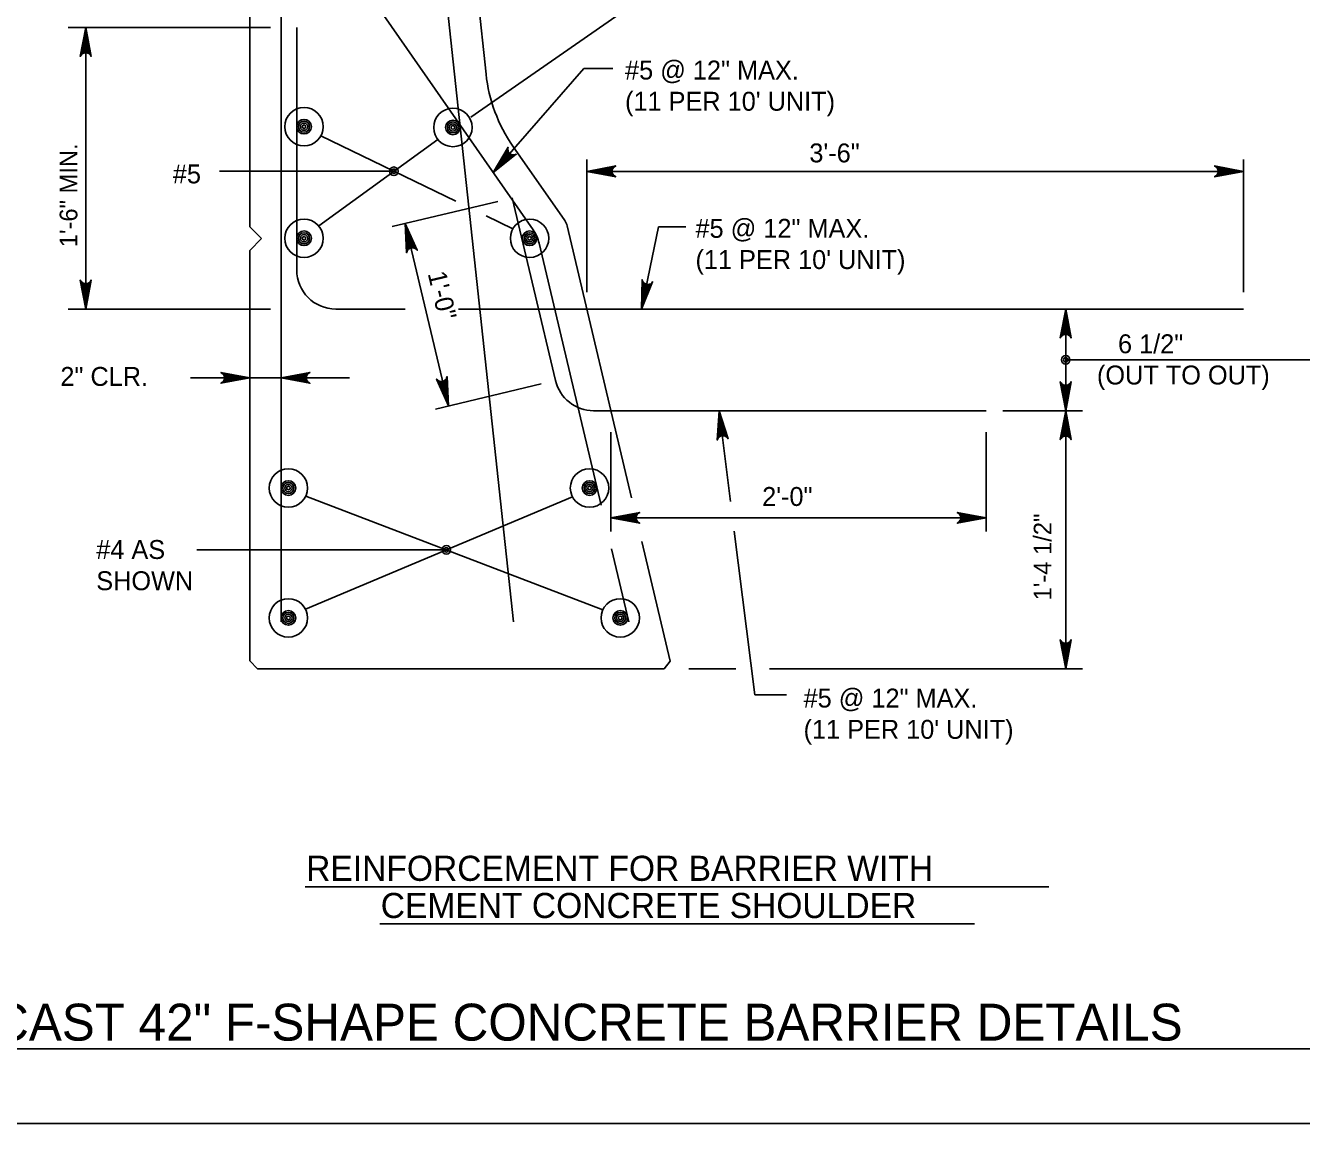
# Model space of a CAD drawing. Extents: x 638167 to 640248, y 296544 to 298920.
# Drawn here: x 638355.5 to 638562.8, y 297153.5 to 297331.8 of the extents above; entities that cross this region are included whole.
import ezdxf

# ---------------------------------------------------------------- set-up
doc = ezdxf.new("R2010")
doc.units = 0
for name, color, linetype in [('1', 7, 'Continuous'), ('50', 7, 'Continuous'), ('57', 7, 'Continuous')]:
    doc.layers.add(name, color=color, linetype=linetype)

# ---------------------------------------------------------------- blocks, each defined once
blk = doc.blocks.new('DIMDOT')
at = {"layer": '57'}
for radius in [2, 1]:
    blk.add_circle((0, 0), radius, dxfattribs=at)
blk = doc.blocks.new('BAR')
at = {"layer": '50'}
for radius in [2, 1.5, 1, 0.5]:
    blk.add_circle((0, 0), radius, dxfattribs=at)

msp = doc.modelspace()

# ---------------------------------------------------------------- linework, layer by layer
at = {"layer": '1'}
for p, q in [((638391.93, 297396.88), (638391.93, 297299.09)), ((638422.65, 297396.51), (638430.31, 297323.92)), ((638397.01, 297234.95), (638397.01, 297389.89)), ((638418.01, 297390.3), (638434.79, 297234.95)), ((638408.65, 297340.68), (638437.96, 297298.6)), ((638427.85, 297316.9), (638456.9, 297337.13)), ((638395.32, 297331.47), (638362.42, 297331.47)), ((638365.28, 297331.47), (638365.28, 297285.75)), ((638399.55, 297292.1), (638399.55, 297331.47)), ((638446.22, 297324.82), (638431.47, 297307.92)), ((638446.22, 297324.82), (638450.88, 297324.82)), ((638403.12, 297299.26), (638422.47, 297313.31)), ((638403.47, 297313.86), (638425.4, 297303.25)), ((638434.67, 297312.21), (638443.09, 297300.12)), ((638446.67, 297288.51), (638446.67, 297310.06)), ((638553.35, 297288.51), (638553.35, 297310.06)), ((638386.99, 297308.12), (638415.33, 297308.12)), ((638446.67, 297308.11), (638553.35, 297308.11)), ((638432.25, 297303.24), (638415.08, 297299.17)), ((638434.57, 297303.79), (638441.6, 297274.13)), ((638430.31, 297300.87), (638434.66, 297298.77)), ((638391.93, 297299.09), (638393.84, 297297.18)), ((638417.18, 297299.67), (638424.21, 297270.01)), ((638443.48, 297299.25), (638453.94, 297255.08)), ((638458.33, 297299.12), (638455.56, 297285.75)), ((638462.76, 297299.12), (638458.33, 297299.12)), ((638391.93, 297295.28), (638393.84, 297297.18)), ((638438.92, 297296.44), (638449, 297253.91)), ((638391.93, 297295.28), (638391.93, 297228.6)), ((638395.32, 297285.75), (638362.42, 297285.75)), ((638405.9, 297285.75), (638417.17, 297285.75)), ((638425.86, 297285.75), (638553.35, 297285.75)), ((638524.47, 297285.75), (638524.47, 297227.33)), ((638524.47, 297277.5), (638564.39, 297277.5)), ((638382.31, 297274.57), (638408.14, 297274.57)), ((638439.28, 297273.58), (638422.1, 297269.51)), ((638447.78, 297269.24), (638511.55, 297269.24)), ((638470.02, 297254.5), (638468.16, 297269.24)), ((638514.24, 297269.24), (638527.2, 297269.24)), ((638450.59, 297265.76), (638450.59, 297249.64)), ((638511.55, 297265.76), (638511.55, 297249.64)), ((638444.34, 297255.27), (638400.99, 297237)), ((638401.04, 297255.38), (638449.28, 297236.9)), ((638450.59, 297251.85), (638511.55, 297251.85)), ((638473.98, 297223.07), (638470.63, 297249.69)), ((638383.34, 297246.64), (638423.86, 297246.64)), ((638450.68, 297246.8), (638453.49, 297234.95)), ((638455.62, 297247.97), (638460.22, 297228.57)), ((638391.93, 297228.6), (638393.2, 297227.33)), ((638460.22, 297228.57), (638459.24, 297227.33)), ((638393.2, 297227.33), (638459.24, 297227.33)), ((638463.26, 297227.33), (638470.91, 297227.33)), ((638476.37, 297227.33), (638527.2, 297227.33)), ((638479.1, 297223.07), (638473.98, 297223.07)), ((638400.95, 297191.93), (638521.73, 297191.93)), ((638413.06, 297185.89), (638509.68, 297185.89)), ((638332.86, 297165.59), (638596.87, 297165.59)), ((638205.78, 297153.48), (638991.78, 297153.48))]:
    msp.add_line(p, q, dxfattribs=at)
for points in [[(638365.28, 297331.47), (638366.16, 297326.78), (638366.04, 297326.96), (638365.91, 297327.14), (638365.76, 297327.23), (638365.6, 297327.33), (638365.44, 297327.35), (638365.28, 297327.38), (638365.13, 297327.35), (638364.97, 297327.33), (638364.81, 297327.23), (638364.65, 297327.14), (638364.53, 297326.96), (638364.4, 297326.78), (638365.28, 297331.47), (638364.53, 297326.96), (638364.65, 297327.14), (638365.28, 297331.47), (638364.81, 297327.23), (638364.97, 297327.33), (638365.28, 297331.47), (638365.13, 297327.35), (638365.28, 297327.38), (638365.28, 297331.47), (638365.44, 297327.35), (638365.6, 297327.33), (638365.28, 297331.47), (638365.76, 297327.23), (638365.91, 297327.14), (638365.28, 297331.47), (638366.04, 297326.96)], [(638431.47, 297307.92), (638433.9, 297312.04), (638433.87, 297311.82), (638433.85, 297311.6), (638433.9, 297311.43), (638433.96, 297311.25), (638434.06, 297311.13), (638434.16, 297311), (638434.3, 297310.92), (638434.44, 297310.84), (638434.62, 297310.8), (638434.8, 297310.77), (638435.01, 297310.82), (638435.22, 297310.88), (638431.47, 297307.92), (638435.01, 297310.82), (638434.8, 297310.77), (638431.47, 297307.92), (638434.62, 297310.8), (638434.44, 297310.84), (638431.47, 297307.92), (638434.3, 297310.92), (638434.16, 297311), (638431.47, 297307.92), (638434.06, 297311.13), (638433.96, 297311.25), (638431.47, 297307.92), (638433.9, 297311.43), (638433.85, 297311.6), (638431.47, 297307.92), (638433.87, 297311.82)], [(638446.67, 297308.11), (638451.37, 297308.99), (638451.19, 297308.87), (638451.01, 297308.74), (638450.92, 297308.58), (638450.82, 297308.43), (638450.8, 297308.27), (638450.77, 297308.11), (638450.8, 297307.95), (638450.82, 297307.8), (638450.92, 297307.64), (638451.01, 297307.48), (638451.19, 297307.36), (638451.37, 297307.23), (638446.67, 297308.11), (638451.19, 297307.36), (638451.01, 297307.48), (638446.67, 297308.11), (638450.92, 297307.64), (638450.82, 297307.8), (638446.67, 297308.11), (638450.8, 297307.95), (638450.77, 297308.11), (638446.67, 297308.11), (638450.8, 297308.27), (638450.82, 297308.43), (638446.67, 297308.11), (638450.92, 297308.58), (638451.01, 297308.74), (638446.67, 297308.11), (638451.19, 297308.87)], [(638553.35, 297308.11), (638548.66, 297307.23), (638548.84, 297307.36), (638549.02, 297307.48), (638549.11, 297307.64), (638549.21, 297307.8), (638549.23, 297307.95), (638549.26, 297308.11), (638549.23, 297308.27), (638549.21, 297308.43), (638549.11, 297308.58), (638549.02, 297308.74), (638548.84, 297308.87), (638548.66, 297308.99), (638553.35, 297308.11), (638548.84, 297308.87), (638549.02, 297308.74), (638553.35, 297308.11), (638549.11, 297308.58), (638549.21, 297308.43), (638553.35, 297308.11), (638549.23, 297308.27), (638549.26, 297308.11), (638553.35, 297308.11), (638549.23, 297307.95), (638549.21, 297307.8), (638553.35, 297308.11), (638549.11, 297307.64), (638549.02, 297307.48), (638553.35, 297308.11), (638548.84, 297307.36)], [(638417.18, 297299.67), (638419.12, 297295.3), (638418.96, 297295.45), (638418.79, 297295.6), (638418.62, 297295.65), (638418.44, 297295.71), (638418.28, 297295.7), (638418.12, 297295.69), (638417.98, 297295.62), (638417.83, 297295.56), (638417.7, 297295.43), (638417.57, 297295.31), (638417.49, 297295.1), (638417.41, 297294.9), (638417.18, 297299.67), (638417.49, 297295.1), (638417.57, 297295.31), (638417.18, 297299.67), (638417.7, 297295.43), (638417.83, 297295.56), (638417.18, 297299.67), (638417.98, 297295.62), (638418.12, 297295.69), (638417.18, 297299.67), (638418.28, 297295.7), (638418.44, 297295.71), (638417.18, 297299.67), (638418.62, 297295.65), (638418.79, 297295.6), (638417.18, 297299.67), (638418.96, 297295.45)], [(638365.28, 297285.75), (638364.4, 297290.45), (638364.53, 297290.27), (638364.65, 297290.09), (638364.81, 297290), (638364.97, 297289.9), (638365.13, 297289.88), (638365.28, 297289.85), (638365.44, 297289.88), (638365.6, 297289.9), (638365.76, 297290), (638365.91, 297290.09), (638366.04, 297290.27), (638366.16, 297290.45), (638365.28, 297285.75), (638366.04, 297290.27), (638365.91, 297290.09), (638365.28, 297285.75), (638365.76, 297290), (638365.6, 297289.9), (638365.28, 297285.75), (638365.44, 297289.88), (638365.28, 297289.85), (638365.28, 297285.75), (638365.13, 297289.88), (638364.97, 297289.9), (638365.28, 297285.75), (638364.81, 297290), (638364.65, 297290.09), (638365.28, 297285.75), (638364.53, 297290.27)], [(638455.56, 297285.75), (638455.65, 297290.53), (638455.74, 297290.33), (638455.82, 297290.13), (638455.96, 297290), (638456.09, 297289.88), (638456.24, 297289.82), (638456.39, 297289.76), (638456.55, 297289.76), (638456.71, 297289.75), (638456.88, 297289.81), (638457.06, 297289.87), (638457.22, 297290.02), (638457.37, 297290.18), (638455.56, 297285.75), (638457.22, 297290.02), (638457.06, 297289.87), (638455.56, 297285.75), (638456.88, 297289.81), (638456.71, 297289.75), (638455.56, 297285.75), (638456.55, 297289.76), (638456.39, 297289.76), (638455.56, 297285.75), (638456.24, 297289.82), (638456.09, 297289.88), (638455.56, 297285.75), (638455.96, 297290), (638455.82, 297290.13), (638455.56, 297285.75), (638455.74, 297290.33)], [(638524.47, 297285.75), (638525.35, 297281.06), (638525.23, 297281.24), (638525.1, 297281.42), (638524.94, 297281.51), (638524.79, 297281.61), (638524.63, 297281.63), (638524.47, 297281.66), (638524.31, 297281.63), (638524.16, 297281.61), (638524, 297281.51), (638523.84, 297281.42), (638523.72, 297281.24), (638523.59, 297281.06), (638524.47, 297285.75), (638523.72, 297281.24), (638523.84, 297281.42), (638524.47, 297285.75), (638524, 297281.51), (638524.16, 297281.61), (638524.47, 297285.75), (638524.31, 297281.63), (638524.47, 297281.66), (638524.47, 297285.75), (638524.63, 297281.63), (638524.79, 297281.61), (638524.47, 297285.75), (638524.94, 297281.51), (638525.1, 297281.42), (638524.47, 297285.75), (638525.23, 297281.24)], [(638391.93, 297274.57), (638387.23, 297273.69), (638387.41, 297273.82), (638387.6, 297273.94), (638387.69, 297274.1), (638387.78, 297274.26), (638387.81, 297274.42), (638387.84, 297274.57), (638387.81, 297274.73), (638387.78, 297274.89), (638387.69, 297275.05), (638387.6, 297275.2), (638387.41, 297275.33), (638387.23, 297275.45), (638391.93, 297274.57), (638387.41, 297275.33), (638387.6, 297275.2), (638391.93, 297274.57), (638387.69, 297275.05), (638387.78, 297274.89), (638391.93, 297274.57), (638387.81, 297274.73), (638387.84, 297274.57), (638391.93, 297274.57), (638387.81, 297274.42), (638387.78, 297274.26), (638391.93, 297274.57), (638387.69, 297274.1), (638387.6, 297273.94), (638391.93, 297274.57), (638387.41, 297273.82)], [(638397.01, 297274.57), (638401.71, 297275.45), (638401.53, 297275.33), (638401.35, 297275.2), (638401.25, 297275.05), (638401.16, 297274.89), (638401.13, 297274.73), (638401.11, 297274.57), (638401.13, 297274.42), (638401.16, 297274.26), (638401.25, 297274.1), (638401.35, 297273.94), (638401.53, 297273.82), (638401.71, 297273.69), (638397.01, 297274.57), (638401.53, 297273.82), (638401.35, 297273.94), (638397.01, 297274.57), (638401.25, 297274.1), (638401.16, 297274.26), (638397.01, 297274.57), (638401.13, 297274.42), (638401.11, 297274.57), (638397.01, 297274.57), (638401.13, 297274.73), (638401.16, 297274.89), (638397.01, 297274.57), (638401.25, 297275.05), (638401.35, 297275.2), (638397.01, 297274.57), (638401.53, 297275.33)], [(638424.21, 297270.01), (638422.27, 297274.38), (638422.43, 297274.23), (638422.59, 297274.09), (638422.77, 297274.03), (638422.94, 297273.98), (638423.1, 297273.99), (638423.26, 297274), (638423.41, 297274.06), (638423.56, 297274.12), (638423.69, 297274.25), (638423.82, 297274.38), (638423.9, 297274.58), (638423.98, 297274.79), (638424.21, 297270.01), (638423.9, 297274.58), (638423.82, 297274.38), (638424.21, 297270.01), (638423.69, 297274.25), (638423.56, 297274.12), (638424.21, 297270.01), (638423.41, 297274.06), (638423.26, 297274), (638424.21, 297270.01), (638423.1, 297273.99), (638422.94, 297273.98), (638424.21, 297270.01), (638422.77, 297274.03), (638422.59, 297274.09), (638424.21, 297270.01), (638422.43, 297274.23)], [(638524.47, 297269.24), (638523.59, 297273.94), (638523.72, 297273.76), (638523.84, 297273.58), (638524, 297273.49), (638524.16, 297273.39), (638524.31, 297273.37), (638524.47, 297273.34), (638524.63, 297273.37), (638524.79, 297273.39), (638524.94, 297273.49), (638525.1, 297273.58), (638525.23, 297273.76), (638525.35, 297273.94), (638524.47, 297269.24), (638525.23, 297273.76), (638525.1, 297273.58), (638524.47, 297269.24), (638524.94, 297273.49), (638524.79, 297273.39), (638524.47, 297269.24), (638524.63, 297273.37), (638524.47, 297273.34), (638524.47, 297269.24), (638524.31, 297273.37), (638524.16, 297273.39), (638524.47, 297269.24), (638524, 297273.49), (638523.84, 297273.58), (638524.47, 297269.24), (638523.72, 297273.76)], [(638468.16, 297269.24), (638469.62, 297264.69), (638469.48, 297264.86), (638469.33, 297265.02), (638469.16, 297265.09), (638468.99, 297265.17), (638468.84, 297265.17), (638468.68, 297265.18), (638468.52, 297265.14), (638468.37, 297265.09), (638468.23, 297264.98), (638468.08, 297264.86), (638467.98, 297264.67), (638467.88, 297264.47), (638468.16, 297269.24), (638467.98, 297264.67), (638468.08, 297264.86), (638468.16, 297269.24), (638468.23, 297264.98), (638468.37, 297265.09), (638468.16, 297269.24), (638468.52, 297265.14), (638468.68, 297265.18), (638468.16, 297269.24), (638468.84, 297265.17), (638468.99, 297265.17), (638468.16, 297269.24), (638469.16, 297265.09), (638469.33, 297265.02), (638468.16, 297269.24), (638469.48, 297264.86)], [(638524.47, 297269.24), (638525.35, 297264.55), (638525.23, 297264.73), (638525.1, 297264.91), (638524.94, 297265), (638524.79, 297265.1), (638524.63, 297265.12), (638524.47, 297265.15), (638524.31, 297265.12), (638524.16, 297265.1), (638524, 297265), (638523.84, 297264.91), (638523.72, 297264.73), (638523.59, 297264.55), (638524.47, 297269.24), (638523.72, 297264.73), (638523.84, 297264.91), (638524.47, 297269.24), (638524, 297265), (638524.16, 297265.1), (638524.47, 297269.24), (638524.31, 297265.12), (638524.47, 297265.15), (638524.47, 297269.24), (638524.63, 297265.12), (638524.79, 297265.1), (638524.47, 297269.24), (638524.94, 297265), (638525.1, 297264.91), (638524.47, 297269.24), (638525.23, 297264.73)], [(638450.59, 297251.85), (638455.28, 297252.73), (638455.1, 297252.61), (638454.92, 297252.48), (638454.83, 297252.33), (638454.73, 297252.17), (638454.71, 297252.01), (638454.68, 297251.85), (638454.71, 297251.7), (638454.73, 297251.54), (638454.83, 297251.38), (638454.92, 297251.22), (638455.1, 297251.1), (638455.28, 297250.97), (638450.59, 297251.85), (638455.1, 297251.1), (638454.92, 297251.22), (638450.59, 297251.85), (638454.83, 297251.38), (638454.73, 297251.54), (638450.59, 297251.85), (638454.71, 297251.7), (638454.68, 297251.85), (638450.59, 297251.85), (638454.71, 297252.01), (638454.73, 297252.17), (638450.59, 297251.85), (638454.83, 297252.33), (638454.92, 297252.48), (638450.59, 297251.85), (638455.1, 297252.61)], [(638511.55, 297251.85), (638506.85, 297250.97), (638507.03, 297251.1), (638507.21, 297251.22), (638507.3, 297251.38), (638507.4, 297251.54), (638507.42, 297251.7), (638507.45, 297251.85), (638507.42, 297252.01), (638507.4, 297252.17), (638507.3, 297252.33), (638507.21, 297252.48), (638507.03, 297252.61), (638506.85, 297252.73), (638511.55, 297251.85), (638507.03, 297252.61), (638507.21, 297252.48), (638511.55, 297251.85), (638507.3, 297252.33), (638507.4, 297252.17), (638511.55, 297251.85), (638507.42, 297252.01), (638507.45, 297251.85), (638511.55, 297251.85), (638507.42, 297251.7), (638507.4, 297251.54), (638511.55, 297251.85), (638507.3, 297251.38), (638507.21, 297251.22), (638511.55, 297251.85), (638507.03, 297251.1)], [(638524.47, 297227.33), (638523.59, 297232.03), (638523.72, 297231.85), (638523.84, 297231.67), (638524, 297231.58), (638524.16, 297231.48), (638524.31, 297231.46), (638524.47, 297231.43), (638524.63, 297231.46), (638524.79, 297231.48), (638524.94, 297231.58), (638525.1, 297231.67), (638525.23, 297231.85), (638525.35, 297232.03), (638524.47, 297227.33), (638525.23, 297231.85), (638525.1, 297231.67), (638524.47, 297227.33), (638524.94, 297231.58), (638524.79, 297231.48), (638524.47, 297227.33), (638524.63, 297231.46), (638524.47, 297231.43), (638524.47, 297227.33), (638524.31, 297231.46), (638524.16, 297231.48), (638524.47, 297227.33), (638524, 297231.58), (638523.84, 297231.67), (638524.47, 297227.33), (638523.72, 297231.85)]]:
    msp.add_lwpolyline(points, dxfattribs=at)
for centre in [(638400.74, 297315.37), (638424.92, 297315.24), (638400.74, 297297.24), (638437.38, 297297.24), (638398.2, 297256.68), (638447.12, 297256.68), (638398.2, 297235.59), (638452.11, 297235.59)]:
    msp.add_circle(centre, 3.12, dxfattribs=at)
for centre, radius, start, end in [((638455.25, 297326.55), 25.08, 186.0207, 214.8545), ((638441.01, 297298.67), 2.54, 13.3245, 34.8545), ((638432.74, 297294.98), 6.35, 13.3245, 34.8545), ((638405.9, 297292.1), 6.35, 180, 270), ((638447.78, 297275.59), 6.35, 193.3245, 270)]:
    msp.add_arc(centre, radius, start, end, dxfattribs=at)

# ---------------------------------------------------------------- block references
at = {"layer": '1', "xscale": 0.5953136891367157, "yscale": 0.5953136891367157, "rotation": -90.00000000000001}
for p in [(638400.74, 297315.37), (638424.92, 297315.24), (638400.74, 297297.24), (638437.38, 297297.24), (638398.2, 297256.68), (638447.12, 297256.68), (638398.2, 297235.59), (638452.11, 297235.59)]:
    msp.add_blockref('BAR', p, dxfattribs=at)
at = {"layer": '1', "xscale": 0.349999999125, "yscale": 0.349999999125}
for p in [(638415.33, 297308.12), (638524.47, 297277.5), (638423.86, 297246.64)]:
    msp.add_blockref('DIMDOT', p, dxfattribs=at)

# ---------------------------------------------------------------- texts
at = {"layer": '1'}
for s, height, p in [('#5 @ 12" MAX.', 3.072, (638452.89, 297323.03)), ("(11 PER 10' UNIT)", 3.072, (638452.89, 297317.96)), ('3\'-6"', 3.072, (638482.83, 297309.57)), ('#5', 3.072, (638379.43, 297306.16)), ('#5 @ 12" MAX.', 3.072, (638464.33, 297297.32)), ("(11 PER 10' UNIT)", 3.072, (638464.33, 297292.25)), ('   6 1/2"', 3.072, (638529.55, 297278.57)), ('2" CLR.', 3.072, (638361.16, 297273.27)), ('(OUT TO OUT)', 3.072, (638529.55, 297273.5)), ('2\'-0"', 3.072, (638475.16, 297253.77)), ('#4 AS', 3.072, (638366.99, 297245.16)), ('SHOWN', 3.072, (638366.99, 297240.09)), ('#5 @ 12" MAX.', 3.072, (638481.89, 297221.03)), ("(11 PER 10' UNIT)", 3.072, (638481.89, 297215.95)), ('REINFORCEMENT FOR BARRIER WITH', 4.08, (638401.08, 297192.88)), ('CEMENT CONCRETE SHOULDER', 4.08, (638413.2, 297186.84)), ('PRECAST 42" F-SHAPE CONCRETE BARRIER DETAILS', 6, (638333.75, 297166.93))]:
    msp.add_text(s, height=height, dxfattribs=at).set_placement(p)
for s, height, rotation, p in [('1\'-6" MIN.', 2.88, 90, (638363.92, 297295.79)), ('1\'-0"', 3, 283.3245, (638420.82, 297291.52)), ('1\'-4 1/2"', 2.88, 90, (638522.16, 297238.44))]:
    msp.add_text(s, height=height, rotation=rotation, dxfattribs=at).set_placement(p)

doc.saveas('drawing.dxf')
